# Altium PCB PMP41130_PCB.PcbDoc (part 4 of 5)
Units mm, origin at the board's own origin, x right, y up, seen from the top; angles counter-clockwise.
Board outline 74.13 x 200.91 mm, 6 copper layers (Top Layer, Layer 1, Inside Layer 1, Inside Layer 2, Layer 2, Bottom Layer), stack 2.208 mm thick; 356 components, 162 nets, 889 pads, 1511 vias.
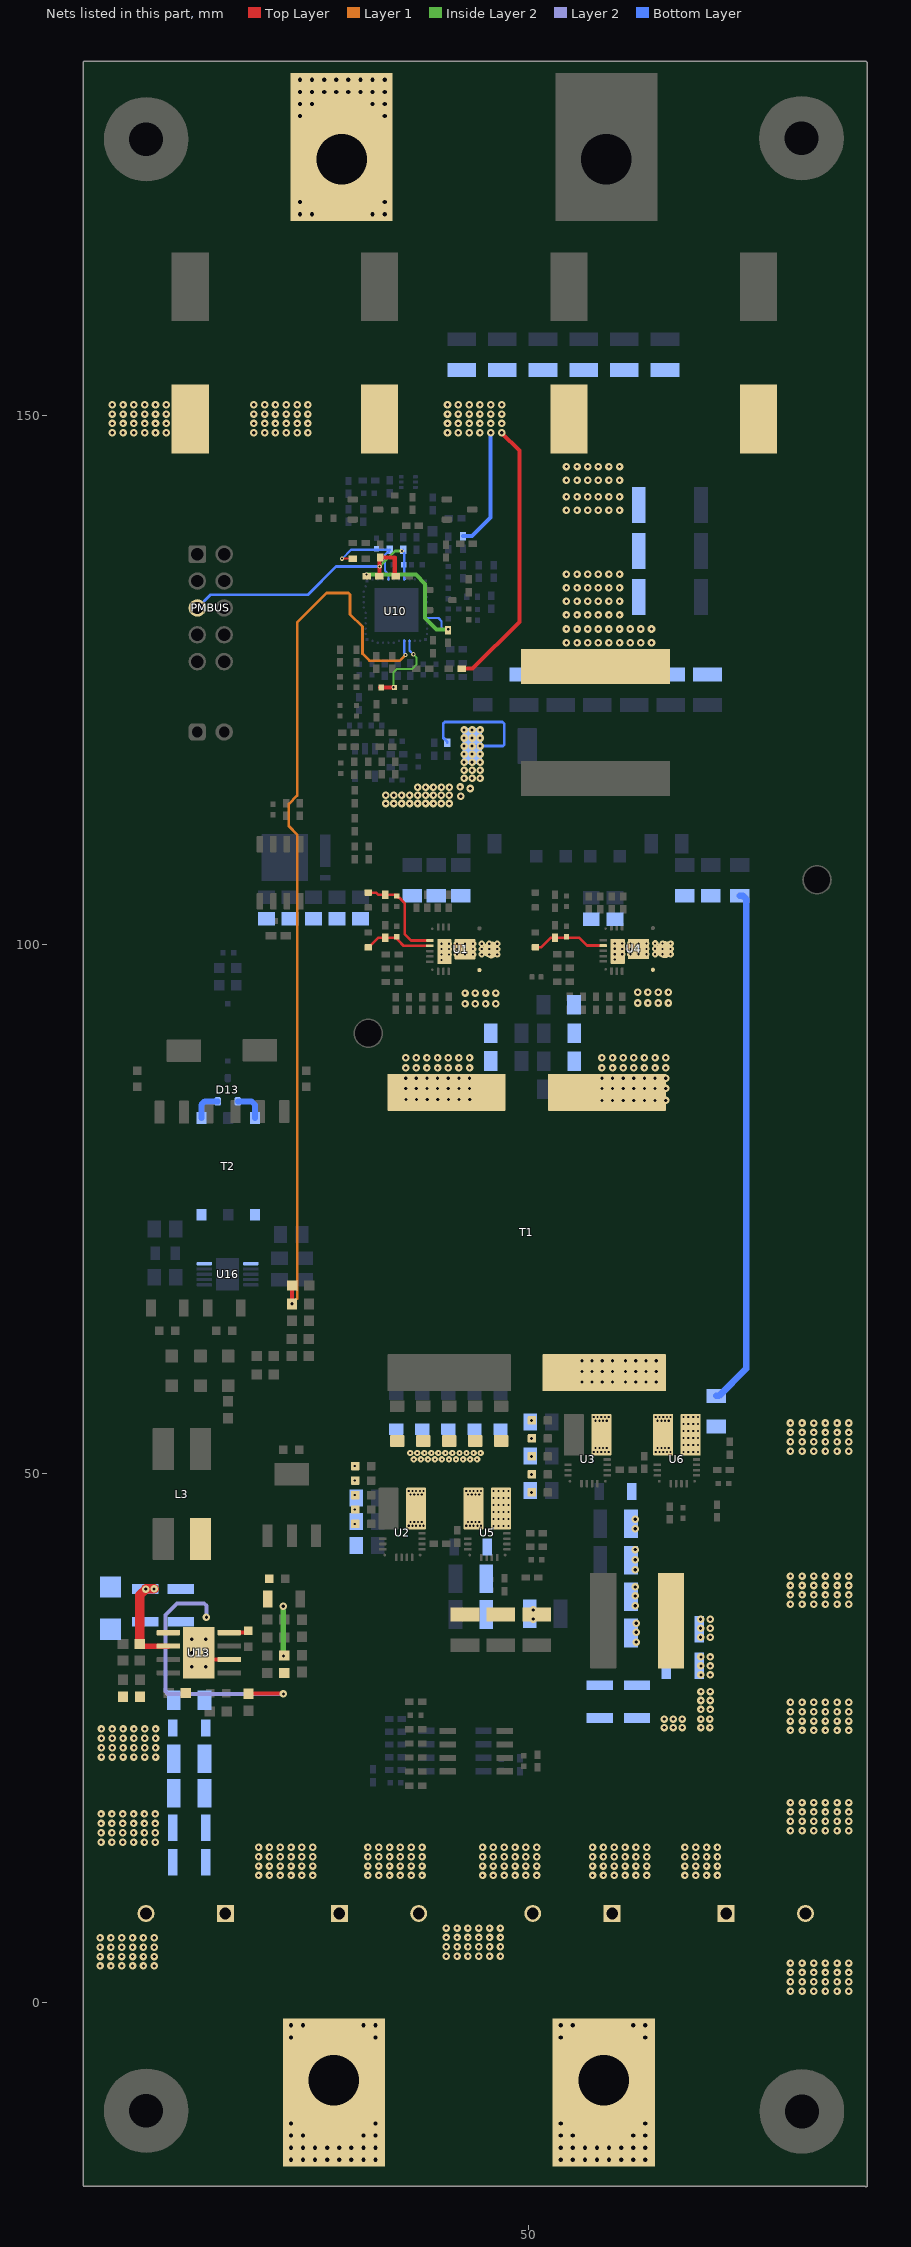
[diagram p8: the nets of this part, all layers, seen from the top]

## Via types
v1: diameter 0.711, hole 0.305, Top Layer to Bottom Layer, tented both sides, 1055 vias
v2: diameter 0.457, hole 0.203, Top Layer to Bottom Layer, tented both sides, 161 vias
v3: diameter 0.813, hole 0.406, Top Layer to Bottom Layer, 112 vias
v4: diameter 0.406, hole 0.203, Top Layer to Bottom Layer, tented both sides, 78 vias
v5: diameter 0.61, hole 0.203, Top Layer to Bottom Layer, tented both sides, 71 vias
v6: diameter 0.5, hole 0.2, Top Layer to Bottom Layer, 28 vias
v7: diameter 0.63, hole 0.33, Top Layer to Bottom Layer, 6 vias

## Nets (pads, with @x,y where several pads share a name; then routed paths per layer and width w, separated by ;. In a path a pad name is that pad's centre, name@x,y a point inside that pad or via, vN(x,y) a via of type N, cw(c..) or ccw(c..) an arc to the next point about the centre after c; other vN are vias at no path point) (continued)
SR_GATE2: C87.1 D4.2 R43.2 U4.13 | length 7.1
  Top Layer w0.254: D4.2@50.658,99.696 50.66,99.698 51.202,99.698 52.095,100.592 52.095,100.6 52.569,100.6 53.594,100.6 54.808,100.6 55.54,99.867 U4.13@57.074,99.867
SR_GATE3: C97.1 D5.2 R61.2 U1.12 | length 9.5
  Top Layer w0.254: D5.2@34.856,104.87 35.604,104.87 35.822,104.652 R61.2@36.472,104.652 36.475,104.656 37.557,104.656 C97.1@37.557,104.555 37.73,104.382 37.792,104.382 38.318,103.856 38.318,100.919 38.895,100.342 U1.12@40.683,100.342
SR_GATE4: C98.1 D6.2 R64.2 U1.13 | length 6.6
  Top Layer w0.254: D6.2@34.856,99.696 34.906,99.696 35.079,99.869 35.079,99.887 35.791,100.6 R64.2@36.472,100.6 C98.1@37.596,100.6 ; C98.1@37.557,100.6 37.557,100.5 37.73,100.327 38.214,99.842 U1.13@40.683,99.842
SR_Source: C3.2 C4.2 C125.1 C141.1 C142.1 C143.1 C144.1 C145.1 R1.2 R2.2 R3.2 R4.2 R5.2 R6.2 R51.2 RSENSE1.1 U1.6 U4.6 | length 62
  Bottom Layer w0.254: R51.2@42.327,119.026 42.327,119.126 41.945,119.508 41.945,120.853 42.095,121.003 47.525,121.003 47.724,120.804 47.724,118.869 47.575,118.721 v1(45.432,118.721) v1(44.675,118.721)
  Bottom Layer w0.635: C125.1@67.752,57.297 68,57.297 70.584,59.882 70.584,104.249 70.252,104.582 R3.2@69.977,104.582
  other v1: 36.507,113.293 37.26,113.293 38.013,113.293 38.765,113.293 39.518,113.293 40.27,113.293 41.023,113.293 41.767,113.293 42.519,113.293 43.595,113.984 36.507,114.069 37.26,114.069 38.013,114.069 38.765,114.069 39.518,114.069 40.27,114.069 41.023,114.069 41.763,114.069 42.515,114.069 44.5,114.71 39.518,114.833 40.27,114.833 41.023,114.833 41.778,114.833 42.531,114.833 43.535,114.864 43.91,115.669 44.668,115.669 45.432,115.669 43.91,116.431 44.668,116.431 45.432,116.431 43.917,117.197 44.675,117.197 45.432,117.197 43.917,117.959 44.675,117.959 45.432,117.959 43.917,118.721 43.917,119.483 44.675,119.483 45.432,119.483 43.917,120.245 44.675,120.245 45.432,120.245
  other v5: 41.77,98.515 58.161,98.54 42.479,99.019 43.241,99.019 44.003,99.019 44.765,99.019 46.289,99.019 47.051,99.019 41.77,99.023 45.58,99.023 58.869,99.044 59.631,99.044 60.393,99.044 61.155,99.044 62.679,99.044 63.441,99.044 58.161,99.048 61.971,99.048 42.479,99.527 43.241,99.527 44.003,99.527 44.765,99.527 46.289,99.527 47.051,99.527 41.77,99.531 45.58,99.531 58.869,99.552 59.631,99.552 60.393,99.552 61.155,99.552 62.679,99.552 63.441,99.552 58.161,99.556 61.971,99.556 42.479,100.035 43.241,100.035 44.003,100.035 44.765,100.035 46.289,100.035 47.051,100.035 41.77,100.039 45.58,100.039 58.869,100.06 59.631,100.06 60.393,100.06 61.155,100.06 62.679,100.06 63.441,100.06 58.161,100.064 61.971,100.064
SW1: C1.1 C7.1 C9.1 C20.1 C21.1 C22.1 C29.1 C32.1 C53.1 C54.1 U2.6 U5.7
  other v2: 38.682,45.023 39.034,45.023 39.386,45.023 39.738,45.023 40.089,45.023 44.114,45.023 44.466,45.023 44.818,45.023 45.17,45.023 45.522,45.023 38.858,45.372 39.21,45.372 39.562,45.372 39.914,45.372 44.29,45.372 44.642,45.372 44.994,45.372 45.346,45.372 38.858,47.968 39.21,47.968 39.562,47.968 39.914,47.968 44.29,47.968 44.642,47.968 44.994,47.968 45.346,47.968 38.682,48.317 39.034,48.317 39.386,48.317 39.738,48.317 40.089,48.317 44.114,48.317 44.466,48.317 44.818,48.317 45.17,48.317 45.522,48.317
  other v5: 39.165,51.289 39.829,51.289 40.494,51.289 41.158,51.289 41.823,51.289 42.488,51.289 43.152,51.289 43.817,51.289 44.482,51.289 45.146,51.289 38.829,51.899 39.493,51.899 40.158,51.899 40.823,51.899 41.487,51.899 42.152,51.899 42.817,51.899 43.481,51.899 44.146,51.899 44.811,51.899 45.475,51.899
SW2: T1.2 U3.6 U6.7
  other v1: 55.051,58.608 56.018,58.608 56.986,58.608 57.954,58.608 59.173,58.608 60.141,58.608 61.109,58.608 62.077,58.608 55.051,59.613 56.018,59.613 56.986,59.613 57.954,59.613 59.173,59.613 60.141,59.613 61.109,59.613 62.077,59.613 55.051,60.619 56.018,60.619 56.986,60.619 57.954,60.619 59.173,60.619 60.141,60.619 61.109,60.619 62.077,60.619
  other v2: 56.177,52.006 56.529,52.006 56.88,52.006 57.232,52.006 57.584,52.006 62.033,52.006 62.385,52.006 62.737,52.006 63.088,52.006 63.44,52.006 56.353,52.356 56.704,52.356 57.056,52.356 57.408,52.356 62.209,52.356 62.561,52.356 62.912,52.356 63.264,52.356 56.353,54.951 56.704,54.951 57.056,54.951 57.408,54.951 62.209,54.951 62.561,54.951 62.912,54.951 63.264,54.951 56.177,55.301 56.529,55.301 56.88,55.301 57.232,55.301 57.584,55.301 62.033,55.301 62.385,55.301 62.737,55.301 63.088,55.301 63.44,55.301
SW3: R21.2 R22.2 R23.2 R24.2 T1.3 U4.5
  other v1: 56.946,85.221 57.951,85.221 58.957,85.221 59.963,85.221 60.969,85.221 61.974,85.221 62.98,85.221 56.943,86.363 57.949,86.363 58.955,86.363 59.96,86.363 60.966,86.363 61.972,86.363 62.978,86.363 56.943,87.331 57.949,87.331 58.955,87.331 59.96,87.331 60.966,87.331 61.972,87.331 62.978,87.331 56.943,88.299 57.949,88.299 58.955,88.299 59.96,88.299 60.966,88.299 61.972,88.299 62.978,88.299 56.943,89.267 57.949,89.267 58.955,89.267 59.96,89.267 60.966,89.267 61.972,89.267 62.978,89.267 60.324,94.434 61.292,94.434 62.26,94.434 63.228,94.434 60.324,95.44 61.292,95.44 62.26,95.44 63.228,95.44
SW4: C30.2 C31.2 T1.4 U1.5
  other v1: 38.413,85.314 39.419,85.314 40.425,85.314 41.43,85.314 42.436,85.314 43.442,85.314 44.448,85.314 38.397,86.363 39.403,86.363 40.409,86.363 41.414,86.363 42.42,86.363 43.426,86.363 44.431,86.363 38.397,87.331 39.403,87.331 40.409,87.331 41.414,87.331 42.42,87.331 43.426,87.331 44.431,87.331 38.397,88.299 39.403,88.299 40.409,88.299 41.414,88.299 42.42,88.299 43.426,88.299 44.431,88.299 38.397,89.267 39.403,89.267 40.409,89.267 41.414,89.267 42.42,89.267 43.426,89.267 44.431,89.267 44.01,94.371 44.978,94.371 45.946,94.371 46.914,94.371 44.01,95.376 44.978,95.376 45.946,95.376 46.914,95.376
SW_AUX: C130.2 L3.4 R114.2 U13.8 | length 29.5
  Top Layer w0.381: U13.8@21.449,34.931 23.319,34.931 C130.2@23.514,35.126 ; R114.2@23.518,29.153 26.831,29.153 v1@26.84,29.161
  Layer 2 w0.381: v1(19.557,36.38) 19.557,37.461 19.334,37.684 16.759,37.684 15.678,36.603 15.678,29.344 15.901,29.121 v1(26.84,29.121)
TEMP: C118.1 FB6.2 U10.3 | length 7.7
  Top Layer w0.381: FB6.2@35.973,124.254 C118.1@37.247,124.254
  Inside Layer 2 w0.203: v4(37.239,124.278) 37.239,125.709 37.525,125.995 38.988,125.995 39.433,126.44 39.433,127.08 39.12,127.393 v4(39.12,127.4)
  Bottom Layer w0.203: U10.3@38.761,128.67 38.761,127.759 v4(39.12,127.4)
TMS: C120.1 R98.1 R104.2 U10.24 | length 9
  Top Layer w0.203: v4(32.385,136.434) R98.1@33.407,136.434
  Bottom Layer w0.203: v4(32.385,136.434) 33.225,137.274 35.646,137.274 36.696,137.274 R104.2@36.763,137.207 ; U10.24@36.761,134.474 36.761,134.983 36.44,135.304 36.44,136.819 36.596,136.976 36.696,136.976 36.795,137.075 36.795,137.175 R104.2@36.894,137.274
TransB1: T2.1 U16.1
TransB3: T2.3 U16.10
TransB4: D13.2 T2.4 | length 2.9
  Bottom Layer w0.559: T2.4@19.081,83.562 19.081,84.812 19.408,85.139 D13.2@20.633,85.139
TransB6: D13.1 T2.6 | length 3
  Bottom Layer w0.559: D13.1@22.533,85.139 23.824,85.139 24.151,84.812 24.151,83.571 T2.6@24.161,83.562
V33A: C104.1 C105.1 R70.2 U10.37 | length 14.6
  Inside Layer 2 w0.381: v4(34.695,134.931) 39.369,134.931 40.239,134.061 40.239,130.844 41.323,129.76 v4(42.419,129.76)
  Bottom Layer w0.203: U10.37@40.423,130.82 41.491,130.82 41.781,130.53 41.781,129.886 41.9,129.767 C105.1@42.412,129.767
V33D: C99.1 C102.1 C103.1 PMBUS.5 R67.1 R70.1 U10.27 | length 29.5
  Top Layer w0.381: R70.1@35.898,134.757 35.935,134.794 35.935,136.472 R67.1@36.007,136.544 37.362,136.544 37.362,134.866 C99.1@37.472,134.757
  Inside Layer 2 w0.254: v4(35.935,135.694) 37.398,137.157 38.007,137.157 v4@38.036,137.128
  Bottom Layer w0.203: v4(38.034,137.157) 38.095,137.095 38.141,137.095 38.261,136.976 U10.27@38.261,134.483 ; C102.1@38.157,137.157 C102.1@38.157,137.274
  Bottom Layer w0.254: PMBUS.5@18.699,131.778 19.943,133.023 29.145,133.023 31.817,135.694 v4(35.935,135.694)
VIN_NEG: C10.2 C11.2 C12.2 C13.2 C14.1 C15.1 C16.1 C17.1 C18.1 C19.1 C33.2 C34.2 C35.2 C36.2 C37.1 C38.1 C39.2 C40.2 C41.2 C42.2 C43.2 C45.2 C47.2 C48.2 C64.1 C65.1 C66.1 C67.1 C68.1 C69.1 C70.1 C71.1 C72.1 C73.1 C123.1 C124.1 C125.2 C133.2 C135.2 C136.2 C137.2 C138.2 C155.2 C156.2 C157.2 C158.2 C159.2 C160.1 D11.2 R117.1 R120.1 R121.1 R122.1 T5.1 U5.6 U6.6 U13.1 U13.6 U13.9 | length 7.9
  Top Layer w0.381: U13.9@18.575,33.026 19.21,32.391 U13.6@21.449,32.391
  Inside Layer 2 w0.508: v1(26.813,37.413) 26.826,37.399 26.826,32.725 v1(26.84,32.711)
  other v1: 74.768,1.025 75.87,1.025 76.972,1.025 78.074,1.025 79.177,1.025 80.279,1.025 74.768,1.913 75.87,1.913 76.972,1.913 78.074,1.913 79.177,1.913 80.279,1.913 74.768,2.8 75.87,2.8 76.972,2.8 78.074,2.8 79.177,2.8 80.279,2.8 9.508,3.411 10.532,3.411 11.556,3.411 12.579,3.411 13.603,3.411 14.626,3.411 74.768,3.688 75.87,3.688 76.972,3.688 78.074,3.688 79.177,3.688 80.279,3.688 9.508,4.299 10.532,4.299 11.556,4.299 12.579,4.299 13.603,4.299 14.626,4.299 42.231,4.333 43.255,4.333 44.279,4.333 45.302,4.333 46.326,4.333 47.349,4.333 9.508,5.186 10.532,5.186 11.556,5.186 12.579,5.186 13.603,5.186 14.626,5.186 42.231,5.221 43.255,5.221 44.279,5.221 45.302,5.221 46.326,5.221 47.349,5.221 9.508,6.074 10.532,6.074 11.556,6.074 12.579,6.074 13.603,6.074 14.626,6.074 42.231,6.108 43.255,6.108 44.279,6.108 45.302,6.108 46.326,6.108 47.349,6.108 42.231,6.996 43.255,6.996 44.279,6.996 45.302,6.996 46.326,6.996 47.349,6.996 9.604,15.114 10.627,15.114 11.651,15.114 12.675,15.114 13.698,15.114 14.722,15.114 9.604,16.001 10.627,16.001 11.651,16.001 12.675,16.001 13.698,16.001 14.722,16.001 74.768,16.194 75.87,16.194 76.972,16.194 78.074,16.194 79.177,16.194 80.279,16.194 9.604,16.889 10.627,16.889 11.651,16.889 12.675,16.889 13.698,16.889 14.722,16.889 74.768,17.081 75.87,17.081 76.972,17.081 78.074,17.081 79.177,17.081 80.279,17.081 9.604,17.777 10.627,17.777 11.651,17.777 12.675,17.777 13.698,17.777 14.722,17.777 74.768,17.969 75.87,17.969 76.972,17.969 78.074,17.969 79.177,17.969 80.279,17.969 74.768,18.857 75.87,18.857 76.972,18.857 78.074,18.857 79.177,18.857 80.279,18.857 9.636,23.159 10.659,23.159 11.683,23.159 12.706,23.159 13.73,23.159 14.754,23.159 9.636,24.047 10.659,24.047 11.683,24.047 12.706,24.047 13.73,24.047 14.754,24.047 9.636,24.935 10.659,24.935 11.683,24.935 12.706,24.935 13.73,24.935 14.754,24.935 74.768,25.67 75.87,25.67 76.972,25.67 78.074,25.67 79.177,25.67 80.279,25.67 9.636,25.822 10.659,25.822 11.683,25.822 12.706,25.822 13.73,25.822 14.754,25.822 74.768,26.558 75.87,26.558 76.972,26.558 78.074,26.558 79.177,26.558 80.279,26.558 74.768,27.446 75.87,27.446 76.972,27.446 78.074,27.446 79.177,27.446 80.279,27.446 74.768,28.334 75.87,28.334 76.972,28.334 78.074,28.334 79.177,28.334 80.279,28.334 60.199,34.027 60.199,34.949 60.199,35.808 50.457,36.202 50.457,37.06 60.104,37.461 74.768,37.597 75.87,37.597 76.972,37.597 78.074,37.597 79.177,37.597 80.279,37.597 60.104,38.384 74.768,38.485 75.87,38.485 76.972,38.485 78.074,38.485 79.177,38.485 80.279,38.485 60.104,39.242 74.768,39.373 75.87,39.373 76.972,39.373 78.074,39.373 79.177,39.373 80.279,39.373 74.768,40.26 75.87,40.26 76.972,40.26 78.074,40.26 79.177,40.26 80.279,40.26 60.104,40.864 60.104,41.818 60.104,42.772 60.104,44.744 60.104,45.634 50.284,48.169 50.284,49.87 50.284,51.571 74.768,52.07 75.87,52.07 76.972,52.067 78.074,52.07 79.177,52.07 79.177,52.07 80.279,52.07 74.768,52.958 75.87,52.958 76.972,52.954 78.074,52.958 79.177,52.958 79.177,52.958 80.279,52.958 50.284,53.272 74.768,53.846 75.87,53.846 76.972,53.842 78.074,53.846 79.177,53.846 79.177,53.846 80.279,53.846 74.768,54.733 75.87,54.733 76.972,54.73 78.074,54.733 79.177,54.733 79.177,54.733 80.279,54.733 50.284,54.973
  other v2: 46.706,45 47.171,45 47.637,45 48.102,45 33.576,45.189 46.706,45.66 47.171,45.66 47.637,45.66 48.102,45.66 46.706,46.319 47.171,46.319 47.637,46.319 48.102,46.319 33.576,46.556 46.706,46.978 47.171,46.978 47.637,46.978 48.102,46.978 46.706,47.637 47.171,47.637 47.637,47.637 48.102,47.637 33.576,47.924 46.706,48.296 47.171,48.296 47.637,48.296 48.102,48.296 33.576,49.291 33.576,50.659 64.644,52.007 65.11,52.007 65.575,52.007 66.04,52.007 64.644,52.666 65.11,52.666 65.575,52.666 66.04,52.666 64.644,53.325 65.11,53.325 65.575,53.325 66.04,53.325 64.644,53.984 65.11,53.984 65.575,53.984 66.04,53.984 64.644,54.644 65.11,54.644 65.575,54.644 66.04,54.644 64.644,55.303 65.11,55.303 65.575,55.303 66.04,55.303
  other v3: 53.05,-14.903 54.193,-14.903 55.336,-14.903 56.479,-14.903 57.622,-14.903 58.765,-14.903 59.908,-14.903 61.051,-14.903 53.05,-13.76 54.193,-13.76 55.336,-13.76 56.479,-13.76 57.622,-13.76 58.765,-13.76 59.908,-13.76 61.051,-13.76 53.05,-12.617 54.193,-12.617 59.908,-12.617 61.051,-12.617 53.05,-11.474 61.051,-11.474 53.05,-3.346 61.051,-3.346 53.05,-2.203 54.193,-2.203 59.908,-2.203 61.051,-2.203
  other v7: 18.189,31.71 19.489,31.71 18.189,33.01 19.489,33.01 18.189,34.31 19.489,34.31
VIN_POS: C10.1 C11.1 C12.1 C13.1 C33.1 C34.1 C35.1 C36.1 C137.1 C138.1 C155.1 C156.1 C157.1 C158.1 C159.1 C160.2 D11.1 L1.1 R113.2 T3.1 U13.2 | length 9
  Top Layer w0.508: R113.2@13.273,33.887 13.514,33.645 U13.2@15.964,33.645
  Top Layer w0.889: R113.2@13.257,33.887 13.257,38.464 13.818,39.025 v1(13.818,39.041) 13.824,39.047 14.608,39.047 v1(14.614,39.054)
  other v1: 24.487,11.965 25.51,11.965 26.534,11.965 27.557,11.965 28.581,11.965 29.604,11.965 34.822,11.965 35.845,11.965 36.869,11.965 37.893,11.965 38.916,11.965 39.94,11.965 45.66,11.965 46.683,11.965 47.707,11.965 48.73,11.965 49.754,11.965 50.777,11.965 56.065,11.965 57.088,11.965 58.112,11.965 59.136,11.965 60.159,11.965 61.183,11.965 64.79,11.965 65.814,11.965 66.837,11.965 67.861,11.965 24.487,12.853 25.51,12.853 26.534,12.853 27.557,12.853 28.581,12.853 29.604,12.853 34.822,12.853 35.845,12.853 36.869,12.853 37.893,12.853 38.916,12.853 39.94,12.853 45.66,12.853 46.683,12.853 47.707,12.853 48.73,12.853 49.754,12.853 50.777,12.853 56.065,12.853 57.088,12.853 58.112,12.853 59.136,12.853 60.159,12.853 61.183,12.853 64.79,12.853 65.814,12.853 66.837,12.853 67.861,12.853 24.487,13.741 25.51,13.741 26.534,13.741 27.557,13.741 28.581,13.741 29.604,13.741 34.822,13.741 35.845,13.741 36.869,13.741 37.893,13.741 38.916,13.741 39.94,13.741 45.66,13.741 46.683,13.741 47.707,13.741 48.73,13.741 49.754,13.741 50.777,13.741 56.065,13.741 57.088,13.741 58.112,13.741 59.136,13.741 60.159,13.741 61.183,13.741 64.79,13.741 65.814,13.741 66.837,13.741 67.861,13.741 24.487,14.628 25.51,14.628 26.534,14.628 27.557,14.628 28.581,14.628 29.604,14.628 34.822,14.628 35.845,14.628 36.869,14.628 37.893,14.628 38.916,14.628 39.94,14.628 45.66,14.628 46.683,14.628 47.707,14.628 48.73,14.628 49.754,14.628 50.777,14.628 56.065,14.628 57.088,14.628 58.112,14.628 59.136,14.628 60.159,14.628 61.183,14.628 64.79,14.628 65.814,14.628 66.837,14.628 67.861,14.628 62.838,25.949 63.688,25.949 64.537,25.949 66.3,25.949 67.149,25.949 62.843,26.748 63.693,26.748 64.542,26.748 66.305,26.748 67.154,26.748 66.305,27.654 67.195,27.654 66.305,28.503 67.195,28.503 66.305,29.352 67.195,29.352 66.305,30.92 67.195,30.92 66.305,31.769 67.195,31.769 66.305,32.618 67.195,32.618 66.273,34.482 67.195,34.482 66.273,35.331 67.195,35.331 66.273,36.18 67.195,36.18
  other v3: 27.546,-14.903 28.689,-14.903 29.832,-14.903 30.975,-14.903 32.118,-14.903 33.261,-14.903 34.404,-14.903 35.547,-14.903 27.546,-13.76 28.689,-13.76 29.832,-13.76 30.975,-13.76 32.118,-13.76 33.261,-13.76 34.404,-13.76 35.547,-13.76 27.546,-12.617 28.689,-12.617 34.404,-12.617 35.547,-12.617 27.546,-11.474 35.547,-11.474 27.546,-3.346 35.547,-3.346 27.546,-2.203 28.689,-2.203 34.404,-2.203 35.547,-2.203
VIN_Scale: C140.1 R126.2 U10.4 | length 85.3
  Top Layer w0.381: R126.2@27.632,65.981 v1(27.657,66.007) 27.657,67.701 C140.1@27.683,67.726
  Layer 1 w0.254: v1(27.657,66.007) 28.144,66.493 28.144,110.349 27.349,111.144 27.349,113.243 28.144,114.038 28.144,130.415 30.91,133.182 32.988,133.182 33.136,133.033 33.136,131.178 34.313,130.002 34.313,127.458 34.981,126.79 37.838,126.79 v4(38.381,127.333)
  Bottom Layer w0.203: U10.4@38.261,128.67 38.261,127.508 38.381,127.388 v4(38.381,127.333)
VOUT: C23.2 C24.2 C25.2 C26.2 C27.2 C28.2 C49.1 C50.1 C51.1 C52.1 C57.2 C58.2 C59.2 C60.2 C61.2 C62.2 L2.2 R7.2 R8.1 R10.2 R71.2 R74.2 T4.1 | length 37.5
  Top Layer w0.381: R74.2@43.675,126.028 43.692,126.045 44.73,126.045 49.132,130.447 49.132,146.661 v1(47.466,148.327)
  Top Layer w0.508: L2.2@56.14,126.028 L2.2@56.351,126.238
  Bottom Layer w0.381: R71.2@43.807,138.557 44.65,138.557 46.435,140.342 v1@46.435,148.319
  other v1: 53.586,128.496 54.591,128.496 55.597,128.496 56.603,128.496 57.609,128.496 58.614,128.496 59.62,128.496 60.626,128.496 61.631,128.496 53.586,129.786 54.591,129.786 55.597,129.786 56.603,129.786 57.609,129.786 58.614,129.786 59.62,129.786 60.626,129.786 61.631,129.786 53.586,131.121 54.591,131.121 55.597,131.121 56.603,131.121 57.609,131.121 58.614,131.121 53.586,132.411 54.591,132.411 55.597,132.411 56.603,132.411 57.609,132.411 58.614,132.411 53.586,133.68 54.591,133.68 55.597,133.68 56.603,133.68 57.609,133.68 58.614,133.68 53.586,134.971 54.591,134.971 55.597,134.971 56.603,134.971 57.609,134.971 58.614,134.971 53.586,141.007 54.591,141.007 55.597,141.007 56.603,141.007 57.609,141.007 58.614,141.007 53.586,142.298 54.591,142.298 55.597,142.298 56.603,142.298 57.609,142.298 58.614,142.298 53.586,143.849 54.591,143.849 55.597,143.849 56.603,143.849 57.609,143.849 58.614,143.849 53.586,145.139 54.591,145.139 55.597,145.139 56.603,145.139 57.609,145.139 58.614,145.139 10.653,148.327 11.677,148.327 12.7,148.327 13.724,148.327 14.748,148.327 15.771,148.327 24.041,148.327 25.065,148.327 26.089,148.327 27.112,148.327 28.136,148.327 29.159,148.327 42.349,148.327 43.372,148.327 44.396,148.327 45.419,148.327 46.443,148.327 10.653,149.215 11.677,149.215 12.7,149.215 13.724,149.215 14.748,149.215 15.771,149.215 24.041,149.215 25.065,149.215 26.089,149.215 27.112,149.215 28.136,149.215 29.159,149.215 42.349,149.215 43.372,149.215 44.396,149.215 45.419,149.215 46.443,149.215 47.466,149.215 10.653,150.102 11.677,150.102 12.7,150.102 13.724,150.102 14.748,150.102 15.771,150.102 24.041,150.102 25.065,150.102 26.089,150.102 27.112,150.102 28.136,150.102 29.159,150.102 42.349,150.102 43.372,150.102 44.396,150.102 45.419,150.102 46.443,150.102 47.466,150.102 10.653,150.99 11.677,150.99 12.7,150.99 13.724,150.99 14.748,150.99 15.771,150.99 24.041,150.99 25.065,150.99 26.089,150.99 27.112,150.99 28.136,150.99 29.159,150.99 42.349,150.99 43.372,150.99 44.396,150.99 45.419,150.99 46.443,150.99 47.466,150.99
  other v3: 28.404,168.998 29.547,168.998 35.262,168.998 36.405,168.998 28.404,170.141 36.405,170.141 28.404,178.269 36.405,178.269 28.404,179.412 29.547,179.412 35.262,179.412 36.405,179.412 28.404,180.555 29.547,180.555 30.69,180.555 31.833,180.555 32.976,180.555 34.119,180.555 35.262,180.555 36.405,180.555 28.404,181.698 29.547,181.698 30.69,181.698 31.833,181.698 32.976,181.698 34.119,181.698 35.262,181.698 36.405,181.698
pads on no net: H1.1 H2.1 H3.1 H4.1 H5.0 H6.0 H7.0 H8.0 PMBUS.1 PMBUS.2 PMBUS.3 PMBUS.4 Q2.1 Q2.2 Q2.6 U2.1 U2.5 U2.9 U2.10 U2.11 U2.12 U2.13 U2.15 U3.1 U3.5 U3.9 U3.10 U3.11 U3.12 U3.13 U3.15 U5.1 U5.5 U5.11 U5.12 U5.13 U5.15 U6.1 U6.5 U6.11 U6.12 U6.13 U6.15 U10.21 U10.22 U10.23 U10.25 U10.39 U16.5 U16.6

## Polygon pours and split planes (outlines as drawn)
NetC30_1 on Bottom Layer "BOTTOM_LAYER_NETC30_1_P012" (solid, remove dead copper, pour order 12): 52.398,95.202 52.398,85.136 48.601,85.136 48.601,95.202
SR_Source on Bottom Layer "BOTTOM_LAYER_SR_SOURCE_P010" (solid, remove dead copper, pour order 10): 20 vertices, not listed, extent 23.66,97.726 70.936,105.233
SR_Drain on Bottom Layer "BOTTOM_LAYER_SR_DRAIN_P024" (solid, remove dead copper, pour order 24): 49.646,114.037 46.114,110.506 46.114,109.745 62.489,109.745 62.489,111.46 62.489,114.037
SR_Source on Bottom Layer "BOTTOM_LAYER_SR_SOURCE_P196" (solid, remove dead copper, pour order 196): 43.44,112.925 44.521,112.925 45.92,114.324 45.92,120.617 43.44,120.617
NetC89_2 on Bottom Layer "BOTTOM_LAYER_NETC89_2_P026" (solid, remove dead copper, pour order 26): 37.773,116.197 37.773,116.907 38.641,116.907 38.641,117.091 38.65,117.1 40.471,117.1 40.471,116.907 42.033,116.907 42.033,118.23 42.622,118.23 42.622,116.197
GND on Bottom Layer "BOTTOM_LAYER_GND_P126" (solid, remove dead copper, pour order 126): 9.68,112.944 8.586,114.038 8.586,140.941 10.971,143.326 46.6,143.326 46.6,123.769 44.489,123.769 44.489,121.924 40.532,121.924 40.532,118.871 35.501,118.871 35.501,112.944
SR_Drain on Bottom Layer "BOTTOM_LAYER_SR_DRAIN_P018" (solid, remove dead copper, pour order 18): 62.485,110.508 46.114,110.508 46.114,102.499 47.818,102.499 47.818,107.687 51.558,107.687 51.558,109.46 57.816,109.46 57.816,107.687 58.116,107.388 60.802,107.388 60.802,102.499 62.485,102.499
GND on Bottom Layer "BOTTOM_LAYER_GND_P092" (solid, remove dead copper, pour order 92): 8.529,73.333 31.61,73.333 31.61,27.444 32.708,26.346 41.93,26.346 42.337,25.939 42.337,18.709 42.009,18.381 30.37,18.381 29.861,18.89 29.861,43.503 28.823,44.542 8.529,44.542
VIN_NEG on Bottom Layer "BOTTOM_LAYER_VIN_NEG_P107" (solid, remove dead copper, pour order 107): 23 vertices, not listed, extent 38.686,-15.551 81.124,55.524
SW1 on Bottom Layer "BOTTOM_LAYER_SW1_P007" (solid, remove dead copper, pour order 7): 48.333,54.82 48.333,49.589 45.945,49.589 45.761,49.405 45.761,44.776 45.672,44.686 38.445,44.686 38.445,49.31 38.295,49.46 36.062,49.46 36.062,54.82
VIN_NEG on Bottom Layer "BOTTOM_LAYER_VIN_NEG_P009" (solid, remove dead copper, pour order 9): 34.404,51.301 33.105,51.301 33.105,28.944 34.404,28.944
SR_Drain on Bottom Layer "BOTTOM_LAYER_SR_DRAIN_P071" (solid, remove dead copper, pour order 71): 18 vertices, not listed, extent 15.074,81.569 22.179,99.476
VIN_NEG on Bottom Layer "BOTTOM_LAYER_VIN_NEG_P006" (solid, remove dead copper, pour order 6): 50.784,55.683 50.784,35.488 50.498,35.202 45.284,35.202 45.284,44.108 46.461,44.108 46.461,48.686 46.655,48.88 48.978,48.88 48.978,55.683
AGND on Bottom Layer "BOTTOM_LAYER_AGND_P131" (solid, remove dead copper, pour order 131): 64.383,123.387 70.181,123.387 70.789,123.995 70.789,163.234 72.856,165.301 79.963,165.301 81.251,164.013 81.251,117.557 80.735,116.963 64.383,116.963 64.383,123.306
VOUT on Bottom Layer "BOTTOM_LAYER_VOUT_P116" (solid, remove dead copper, pour order 116): 27.508,182.314 27.508,168.35 24.836,165.587 9.437,165.587 8.586,164.586 8.586,149.337 8.586,147.683 37.143,147.683 37.143,168.449 37.143,182.314
VOUT on Bottom Layer "BOTTOM_LAYER_VOUT_P031" (solid, remove dead copper, pour order 31): 19 vertices, not listed, extent 8.046,124.818 68.612,154.902
SR_Source on Bottom Layer "BOTTOM_LAYER_SR_SOURCE_P021" (solid, remove dead copper, pour order 21): 36.138,115.214 36.138,112.921 44.077,112.921 44.077,115.214
VIN_POS on Bottom Layer "BOTTOM_LAYER_VIN_POS_P000" (solid, remove dead copper, pour order 0): 69.612,36.87 65.3,36.87 65.3,28.666 64.389,27.755 55.383,27.755 54.936,27.308 54.936,18.364 68.655,18.364 69.612,19.32
VIN_NEG on Bottom Layer "BOTTOM_LAYER_VIN_NEG_P001" (solid, remove dead copper, pour order 1): 63.799,39.686 63.799,29.55 63.194,28.944 33.105,28.944 33.105,30.92 59.042,30.92 59.042,39.686
VIN_NEG on Bottom Layer "BOTTOM_LAYER_VIN_NEG_P002" (solid, remove dead copper, pour order 2): 81.092,55.524 81.092,38.733 59.042,38.733 59.042,50.806 59.086,50.849 64.397,50.849 64.397,55.524
SW2 on Bottom Layer "BOTTOM_LAYER_SW2_P003" (solid, remove dead copper, pour order 3): 65.3,56.287 65.3,62.364 51.494,62.363 51.494,56.86 55.938,56.86 55.938,51.644 63.697,51.644 63.697,56.001 63.983,56.287
HS_Drain on Bottom Layer "BOTTOM_LAYER_HS_DRAIN_P004" (solid, remove dead copper, pour order 4): 55.238,55.715 55.238,51.04 55.429,50.849 57.496,50.849 57.496,32.237 57.259,31.999 51.586,31.999 51.586,55.529 51.772,55.715
NetC1_2 on Bottom Layer "BOTTOM_LAYER_NETC1_2_P005" (solid, remove dead copper, pour order 5): 50.784,56.86 50.784,62.364 36.062,62.364 36.062,56.86
HS_Drain on Bottom Layer "BOTTOM_LAYER_HS_DRAIN_P008" (solid, remove dead copper, pour order 8): 35.213,48.623 35.213,32.323 35.537,31.999 52.372,31.999 52.372,34.622 44.169,34.622 43.79,35.001 43.79,44.008 43.69,44.108 37.733,44.108 37.733,48.623
SW3 on Bottom Layer "BOTTOM_LAYER_SW3_P011" (solid, remove dead copper, pour order 11): 53.594,95.91 53.594,84.253 63.641,84.253 63.641,95.91
NetC5_1 on Bottom Layer "BOTTOM_LAYER_NETC5_1_P015" (solid, remove dead copper, pour order 15): 63.623,110.405 63.623,106.784 70.951,106.784 70.951,110.405
NetC6_1 on Bottom Layer "BOTTOM_LAYER_NETC6_1_P016" (solid, remove dead copper, pour order 16): 38.074,106.85 44.575,106.85 44.575,110.444 38.074,110.444
SW4 on Bottom Layer "BOTTOM_LAYER_SW4_P017" (solid, remove dead copper, pour order 17): 47.568,95.822 47.568,84.253 37.96,84.253 37.96,95.822
NetC3_1 on Bottom Layer "BOTTOM_LAYER_NETC3_1_P019" (solid, remove dead copper, pour order 19): 59.004,103.734 59.004,105.229 56.518,105.229 56.518,108.833 56.342,109.009 53.017,109.009 52.824,108.815 52.824,107.388 54.926,107.388 55.037,107.258 55.037,103.734
AGND on Bottom Layer "BOTTOM_LAYER_AGND_P020" (solid, remove dead copper, pour order 20): 68.623,123.324 44.744,123.323 44.744,121.924 48.97,121.924 48.97,116.963 66.93,116.963 68.612,118.646
NetC89_1 on Bottom Layer "BOTTOM_LAYER_NETC89_1_P025" (solid, remove dead copper, pour order 25): 37.773,118.299 37.773,117.589 38.641,117.589 38.641,117.405 38.65,117.396 40.471,117.396 41.429,117.396 41.429,118.299
NetC91_1 on Bottom Layer "BOTTOM_LAYER_NETC91_1_P027" (solid, remove dead copper, pour order 27): 37.381,117.589 37.381,119.525 35.279,119.525 35.193,119.438 35.193,117.725 35.329,117.589 35.501,117.589
NetC81_2 on Bottom Layer "BOTTOM_LAYER_NETC81_2_P030" (solid, remove dead copper, pour order 30): 37.386,117.091 37.386,115.155 35.198,115.155 35.198,116.948 35.341,117.091
NetC3_1 on Bottom Layer "BOTTOM_LAYER_NETC3_1_P032" (solid, remove dead copper, pour order 32): 68.567,130.828 65.496,130.828 65.219,131.105 65.219,143.068 65.418,143.267 68.146,143.267 68.548,143.267
SR_Source on Bottom Layer "BOTTOM_LAYER_SR_SOURCE_P035" (solid, remove dead copper, pour order 35): 70.935,96.95 70.358,96.95 69.584,97.724 69.584,102.176 70.935,102.176
VIN_NEG on Bottom Layer "BOTTOM_LAYER_VIN_NEG_P060" (solid, remove dead copper, pour order 60): 8.529,-0.286 16.566,-0.286 16.566,36.698 8.529,36.698
VIN_POS on Bottom Layer "BOTTOM_LAYER_VIN_POS_P061" (solid, remove dead copper, pour order 61): 19.373,7.6 24.741,7.6 24.741,29.448 19.373,29.448
VIN_NEG on Bottom Layer "BOTTOM_LAYER_VIN_NEG_P063" (solid, remove dead copper, pour order 63): 15.678,31.104 20.321,31.104 20.321,36.412 20.035,36.698 15.678,36.698
VIN_POS on Bottom Layer "BOTTOM_LAYER_VIN_POS_P064" (solid, remove dead copper, pour order 64): 21.434,38.256 21.911,37.779 21.911,29.473 20.581,28.144 18.858,28.144 18.858,27.821 18.98,27.698 23.495,27.698 24.748,28.952 24.748,39.171 23.729,40.19 8.898,40.19 8.529,39.821 8.529,38.256
TransB3 on Bottom Layer "BOTTOM_LAYER_TRANSB3_P068" (solid, remove dead copper, pour order 68): 18.607,69.632 18.445,69.795 18.445,75.018 20.157,75.018 20.157,69.715 20.073,69.632
NetC141_2 on Bottom Layer "BOTTOM_LAYER_NETC141_2_P072" (solid, remove dead copper, pour order 72): 29.225,110.444 29.32,110.349 29.32,106.119 29.893,105.547 34.943,105.547 35.261,105.229 35.261,103.903 35.092,103.734 23.66,103.734 23.66,110.276 23.828,110.444
TransB1 on Bottom Layer "BOTTOM_LAYER_TRANSB1_P073" (solid, remove dead copper, pour order 73): 24.518,69.632 24.681,69.795 24.681,75.018 22.969,75.018 22.969,69.715 23.052,69.632
VIN_POS on Bottom Layer "BOTTOM_LAYER_VIN_POS_P099" (solid, remove dead copper, pour order 99): 23 vertices, not listed, extent 19.373,-15.837 69.612,20.347
AGND on Bottom Layer "BOTTOM_LAYER_AGND_P117" (solid, remove dead copper, pour order 117): 41.605,165.301 41.605,156.524 57.563,156.524 69.612,156.524 70.852,155.538 81.124,155.538 81.124,163.679 79.502,165.301
AGND on Bottom Layer "BOTTOM_LAYER_AGND_P118" (solid, remove dead copper, pour order 118): 52.535,182.314 52.535,168.353 52.503,168.353 49.323,165.173 49.323,158.622 65.319,158.622 65.319,165.301 62.171,168.449 62.171,182.314
SR_Drain on Bottom Layer "BOTTOM_LAYER_SR_DRAIN_P128" (solid, remove dead copper, pour order 128): 30.274,110.412 30.274,107.328 30.338,107.264 35.85,107.264 36.052,107.467 36.052,110.412
HS_Drain on Top Layer "TOP_LAYER_HS_DRAIN_P047" (solid, remove dead copper, pour order 47): 51.494,55.654 51.363,55.523 51.363,47.658 53.035,47.658 53.035,50.659 54.272,50.659 55.27,51.592 55.27,55.654
SR_Drain on Top Layer "TOP_LAYER_SR_DRAIN_P216" (solid, remove dead copper, pour order 216): 34.439,110.407 34.439,108.832 36.243,108.832 36.243,110.407
VIN_NEG on Top Layer "TOP_LAYER_VIN_NEG_P215" (solid, remove dead copper, pour order 215): 24.264,35.458 9.856,35.458 8.077,33.68 8.077,23.66 27.221,23.66 30.847,27.285 30.847,41.221 30.268,41.822 24.264,41.822
VIN_POS on Top Layer "TOP_LAYER_VIN_POS_P100" (solid, remove dead copper, pour order 100): 69.696,40.693 62.24,40.693 62.24,16.193 61.201,15.153 61.201,6.297 69.696,6.297
VIN_POS on Top Layer "TOP_LAYER_VIN_POS_P101" (solid, remove dead copper, pour order 101): 21 vertices, not listed, extent 20.48,-15.837 68.67,15.201
VIN_NEG on Top Layer "TOP_LAYER_VIN_NEG_P045" (solid, remove dead copper, pour order 45): 49.624,55.654 49.624,51.007 49.275,50.659 46.601,50.659 46.448,50.506 46.448,44.68 49.212,44.68 50.767,46.235 50.767,55.654
VIN_NEG on Top Layer "TOP_LAYER_VIN_NEG_P048" (solid, remove dead copper, pour order 48): 64.397,55.589 64.462,55.654 81.128,55.654 81.128,51.659 64.397,51.659
HS_Drain on Top Layer "TOP_LAYER_HS_DRAIN_P108" (solid, remove dead copper, pour order 108): 21 vertices, not listed, extent 32.914,31.557 58.354,51.136
SR_Drain on Top Layer "TOP_LAYER_SR_DRAIN_P112" (solid, remove dead copper, pour order 112): 22 vertices, not listed, extent 43.491,101.267 64.524,117.345
GND on Top Layer "TOP_LAYER_GND_P109" (solid, remove dead copper, pour order 109): 17.432,83.064 9.318,83.064 8.173,84.209 8.173,142.425 47.192,142.425 47.192,131.36 44.203,128.487 44.203,125.709 39.592,125.709 39.02,125.136 39.02,115.657 31.13,115.623 31.13,85.83 28.427,83.127
SW_AUX on Top Layer "TOP_LAYER_SW_AUX_P074" (solid, remove dead copper, pour order 74): 17.993,45.789 19.957,45.789 19.957,41.822 23.978,41.822 23.978,34.616 17.993,34.616 17.993,40.68
VOUT on Top Layer "TOP_LAYER_VOUT_P143" (solid, remove dead copper, pour order 143): 48.178,124.627 48.178,127.267 49.164,128.253 50.627,129.715 50.627,151.594 51.931,152.898 51.937,152.892 56.23,152.892 63.281,152.892 63.281,128.414 64.587,127.108 64.587,124.627
PRI_AGND on Top Layer "TOP_LAYER_PRI_AGND_P091" (solid, remove dead copper, pour order 91): 47.984,44.316 49.266,44.316 51.141,46.191 53.035,46.191 53.035,37.439 46.399,37.439 44.704,39.134 44.704,41.334 45.773,42.403 47.626,42.403 47.626,43.957
SW2 on Top Layer "TOP_LAYER_SW2_P043" (solid, remove dead copper, pour order 43): 51.436,57.672 51.363,57.745 51.363,61.245 65.128,61.245 65.128,57.865 64.948,57.672 63.873,57.672 63.683,57.481 63.683,51.644 55.938,51.644 55.938,57.464 55.729,57.672
AGND on Top Layer "TOP_LAYER_AGND_P142" (solid, remove dead copper, pour order 142): 70.789,124.058 70.789,141.704 71.089,142.118 80.838,142.118 81.251,141.704 81.251,118.083 80.877,117.653 71.112,117.653 70.789,117.938
VIN_NEG on Top Layer "TOP_LAYER_VIN_NEG_P104" (solid, remove dead copper, pour order 104): 22 vertices, not listed, extent 38.733,-15.551 81.124,55.649
VIN_NEG on Top Layer "TOP_LAYER_VIN_NEG_P038" (solid, remove dead copper, pour order 38): 32.989,54.061 32.914,53.916 32.914,44.685 34.059,44.685 34.059,51.899 35.7,51.899 35.7,54.061
VIN_NEG on Top Layer "TOP_LAYER_VIN_NEG_P039" (solid, remove dead copper, pour order 39): 42.66,38.915 42.66,35.969 42.793,35.835 53.035,35.835 53.035,37.439 46.128,37.439 44.652,38.915
SW1 on Top Layer "TOP_LAYER_SW1_P042" (solid, remove dead copper, pour order 42): 36.996,51.899 36.889,52.006 36.889,53.973 36.977,54.061 48.242,54.061 48.348,53.955 48.348,52.025 48.223,51.899 46.019,51.899 45.784,51.664 45.784,44.68 38.447,44.68 38.447,51.74 38.288,51.899
NetC1_2 on Top Layer "TOP_LAYER_NETC1_2_P044" (solid, remove dead copper, pour order 44): 32.908,55.654 32.908,61.228 48.348,61.228 48.348,55.734 48.268,55.654
SW4 on Top Layer "TOP_LAYER_SW4_P050" (solid, remove dead copper, pour order 50): 43.491,97.767 43.491,91.065 43.058,90.632 38.751,90.632 36.73,88.611 36.73,84.291 47.86,84.291 47.86,97.427 47.52,97.767
SW3 on Top Layer "TOP_LAYER_SW3_P051" (solid, remove dead copper, pour order 51): 59.882,97.767 59.882,90.943 59.571,90.632 53.877,90.632 51.867,88.623 51.867,84.275 64.465,84.275 64.465,97.767
SR_Source on Top Layer "TOP_LAYER_SR_SOURCE_P052" (solid, remove dead copper, pour order 52): 41.429,100.467 41.386,100.416 41.386,98.134 41.414,98.105 42.688,98.105 43.122,98.539 47.666,98.539 47.733,98.606 47.733,100.364 47.627,100.471
SR_Source on Top Layer "TOP_LAYER_SR_SOURCE_P053" (solid, remove dead copper, pour order 53): 57.82,100.492 57.777,100.441 57.777,98.159 57.805,98.131 59.079,98.131 59.513,98.564 64.056,98.564 64.124,98.632 64.124,100.39 64.017,100.496
VOUT on Top Layer "TOP_LAYER_VOUT_P055" (solid, remove dead copper, pour order 55): 10.653,146.411 9.278,147.786 9.278,152.962 80.424,152.962 80.424,147.079 79.756,146.411
NetD9_2 on Top Layer "TOP_LAYER_NETD9_2_P076" (solid, remove dead copper, pour order 76): 17.925,50.265 21.557,50.265 22.165,50.873 22.165,55.654 20.304,55.654 20.062,55.896 20.062,58.687 19.785,58.963 15.588,58.963 15.429,58.804 15.429,57.278 16.465,57.278 17.925,55.818
GND on Top Layer "TOP_LAYER_GND_P077" (solid, remove dead copper, pour order 77): 14.447,43.441 14.447,45.44 14.614,45.607 16.238,45.607 16.397,45.448 16.397,43.441
GND on Top Layer "TOP_LAYER_GND_P078" (solid, remove dead copper, pour order 78): 22 vertices, not listed, extent 16.176,62.956 30.486,70.716
5V0_SEC on Top Layer "TOP_LAYER_5V0_SEC_P079" (solid, remove dead copper, pour order 79): 19.049,90.982 12.561,90.982 12.498,90.918 12.498,87.579 12.53,87.548 13.484,87.548 13.515,87.579 13.515,88.756 13.611,88.851 19.017,88.851 19.049,88.883
3V3_SEC on Top Layer "TOP_LAYER_3V3_SEC_P080" (solid, remove dead copper, pour order 80): 23.002,91.032 29.489,91.032 29.553,90.968 29.553,87.629 29.521,87.598 28.567,87.598 28.535,87.629 28.535,88.806 28.44,88.901 23.034,88.901 23.002,88.933
PRI_AGND on Top Layer "TOP_LAYER_PRI_AGND_P082" (solid, remove dead copper, pour order 82): 65.537,53.361 69.696,53.361 69.696,52.414 68.465,52.414 68.465,50.659 65.537,50.659
AGND on Top Layer "TOP_LAYER_AGND_P086" (solid, remove dead copper, pour order 86): 10.208,165.301 9.278,164.371 9.278,158.688 80.424,158.688 80.424,164.378 79.502,165.301
PRI_AGND on Top Layer "TOP_LAYER_PRI_AGND_P090" (solid, remove dead copper, pour order 90): 68.757,49.406 68.69,49.338 68.69,44.807 68.594,44.712 65.169,44.712 65,44.881 65,46.084 64.206,46.084 64.206,43.991 64.512,43.685 69.581,43.685 69.696,43.8 69.696,49.406
PRI_AGND on Top Layer "TOP_LAYER_PRI_AGND_P096" (solid, remove dead copper, pour order 96): 24.544,42.8 24.337,43.007 24.337,55.446 24.544,55.654 30.421,55.654 30.486,55.588 30.486,51.776 30.374,51.664 27.625,51.664 27.625,42.8
GND on Top Layer "TOP_LAYER_GND_P097" (solid, remove dead copper, pour order 97): 34.501,28.183 34.059,27.741 34.059,19.907 43.154,19.907 43.154,28.183
VIN_NEG on Top Layer "TOP_LAYER_VIN_NEG_P106" (solid, remove dead copper, pour order 106): 15.995,22.484 17.192,23.923 8.586,23.923 8.586,1.844 8.841,1.59 15.551,1.59 15.995,2.034
AGND on Top Layer "TOP_LAYER_AGND_P113" (solid, remove dead copper, pour order 113): 52.535,182.314 52.535,168.353 52.503,168.353 49.323,165.173 49.323,158.622 65.319,158.622 65.319,165.301 62.171,168.449 62.171,182.314
VIN_POS on Inside Layer 1 "INSIDE_LAYER_1_VIN_POS_P147" (solid, remove dead copper, pour order 147): 21 vertices, not listed, extent 20.48,-15.837 69.507,15.201
SR_AGND on Inside Layer 1 "INSIDE_LAYER_1_SR_AGND_P133" (solid, remove dead copper, pour order 133): 32.939,104.02 32.939,93.335 63.951,93.335 64.778,94.162 64.778,104.02
VIN_NEG on Inside Layer 1 "INSIDE_LAYER_1_VIN_NEG_P212" (solid, remove dead copper, pour order 212): 64.397,55.589 64.462,55.654 67.259,55.654 67.259,52.006 66.911,51.659 64.397,51.659
VIN_NEG on Inside Layer 1 "INSIDE_LAYER_1_VIN_NEG_P211" (solid, remove dead copper, pour order 211): 49.624,55.654 49.624,51.007 49.275,50.659 46.601,50.659 46.448,50.506 46.448,44.68 48.271,44.68 50.867,47.276 50.867,55.654
GND on Inside Layer 1 "INSIDE_LAYER_1_GND_P189" (solid, remove dead copper, pour order 189): 32.978,67.068 9.795,67.068 9,67.863 9,144.312 9.699,145.012 46.22,145.012 47.574,143.657 47.574,121.687 43.122,121.687 43.122,104.264 32.978,104.264
PRI_AGND on Inside Layer 1 "INSIDE_LAYER_1_PRI_AGND_P166" (solid, remove dead copper, pour order 166): 31.51,43.275 50.867,43.275 50.867,49.832 66.972,49.832 66.972,51.252 66.972,55.718 71.197,55.718 71.197,19.401 70.275,18.479 31.51,18.479
NetC1_2 on Inside Layer 1 "INSIDE_LAYER_1_NETC1_2_P194" (solid, remove dead copper, pour order 194): 36.889,57.736 36.889,62.427 48.348,62.427 48.348,57.736
SW3 on Inside Layer 1 "INSIDE_LAYER_1_SW3_P188" (solid, remove dead copper, pour order 188): 59.154,90.215 55.037,90.215 55.037,84.267 63.665,84.267 63.665,90.215
SW4 on Inside Layer 1 "INSIDE_LAYER_1_SW4_P187" (solid, remove dead copper, pour order 187): 43.026,90.628 37.899,90.628 37.899,84.282 47.828,84.282 47.828,90.628
HS_Drain on Inside Layer 1 "INSIDE_LAYER_1_HS_DRAIN_P178" (solid, remove dead copper, pour order 178): 37.811,50.166 35.649,50.166 35.649,44.728 37.811,44.728
HS_Drain on Inside Layer 1 "INSIDE_LAYER_1_HS_DRAIN_P177" (solid, remove dead copper, pour order 177): 55.206,55.654 52.607,55.654 52.607,51.644 55.111,51.644 55.206,51.74
VIN_NEG on Inside Layer 1 "INSIDE_LAYER_1_VIN_NEG_P172" (solid, remove dead copper, pour order 172): 16.058,26.68 8.65,26.68 8.65,1.717 8.904,1.463 15.614,1.463 16.058,1.907
SW2 on Inside Layer 1 "INSIDE_LAYER_1_SW2_P168" (solid, remove dead copper, pour order 168): 51.436,57.736 51.363,57.809 51.363,62.427 64.945,62.427 65.128,62.22 65.128,57.929 64.948,57.736 63.873,57.736 63.683,57.545 63.683,51.644 55.938,51.644 55.938,57.528 55.729,57.736
SW1 on Inside Layer 1 "INSIDE_LAYER_1_SW1_P165" (solid, remove dead copper, pour order 165): 36.996,51.931 36.889,52.038 36.889,54.005 36.977,54.093 48.242,54.093 48.348,53.986 48.348,52.056 48.223,51.931 46.019,51.931 45.784,51.696 45.784,44.712 38.479,44.712 38.479,51.867 38.415,51.931
VOUT on Inside Layer 1 "INSIDE_LAYER_1_VOUT_P154" (solid, remove dead copper, pour order 154): 62.139,127.628 52.655,127.628 52.655,128.277 52.655,146.557 51.529,147.683 8.046,147.683 8.046,154.902 62.139,154.902
VIN_NEG on Inside Layer 1 "INSIDE_LAYER_1_VIN_NEG_P146" (solid, remove dead copper, pour order 146): 23 vertices, not listed, extent 38.686,-15.551 81.124,55.643
AGND on Inside Layer 1 "INSIDE_LAYER_1_AGND_P140" (solid, remove dead copper, pour order 140): 70.757,124.122 70.757,165.078 70.979,165.301 80.933,165.301 81.219,165.014 81.219,118.147 80.846,117.716 71.08,117.716 70.757,118.001
AGND on Inside Layer 1 "INSIDE_LAYER_1_AGND_P119" (solid, remove dead copper, pour order 119): 41.723,165.237 41.723,158.624 80.361,158.624 80.361,164.315 79.438,165.237
AGND on Inside Layer 1 "INSIDE_LAYER_1_AGND_P120" (solid, remove dead copper, pour order 120): 52.471,182.25 52.471,168.29 52.44,168.29 49.259,165.11 49.259,158.559 65.255,158.559 65.255,165.237 62.107,168.385 62.107,182.25
SR_Drain on Layer 1 "LAYER_1_SR_DRAIN_P190" (solid, remove dead copper, pour order 190): 46.021,102.516 46.021,110.944 49.166,114.089 64.269,114.089 64.269,102.516 59.913,102.516 59.913,107.899 57.813,109.999 49.897,109.999 47.828,107.587 47.828,102.516
GND on Layer 1 "LAYER_1_GND_P198" (solid, remove dead copper, pour order 198): 35.191,69.027 33.232,67.068 9.795,67.068 9,67.863 9,144.312 9.699,145.012 46.22,145.012 47.574,143.657 47.574,122.846 44.001,119.73 44.001,105.07 35.191,105.07
VIN_NEG on Layer 1 "LAYER_1_VIN_NEG_P144" (solid, remove dead copper, pour order 144): 19 vertices, not listed, extent 8.586,2.353 81.06,56.446
SW3 on Layer 1 "LAYER_1_SW3_P184" (solid, remove dead copper, pour order 184): 59.882,95.876 59.882,90.943 59.154,90.215 55.037,90.215 55.037,84.238 63.665,84.238 63.665,95.876
SW4 on Layer 1 "LAYER_1_SW4_P181" (solid, remove dead copper, pour order 181): 43.459,95.876 43.459,91.061 42.038,89.64 38.017,89.64 38.017,84.296 47.828,84.296 47.828,95.876
VIN_NEG on Layer 1 "LAYER_1_VIN_NEG_P102" (solid, remove dead copper, pour order 102): 30 vertices, not listed, extent 8.287,-15.551 81.124,34.949
SR_Source on Layer 1 "LAYER_1_SR_SOURCE_P136" (solid, remove dead copper, pour order 136): 43.648,112.63 46.238,115.219 46.238,120.747 38.988,120.747 38.988,114.483 36.03,114.483 36.03,111.144 38.988,108.186 38.988,98.9 39.624,98.264 45.889,98.264 63.761,98.264 64.269,98.773 64.269,100.816 43.648,100.816
VIN_POS on Layer 1 "LAYER_1_VIN_POS_P156" (solid, remove dead copper, pour order 156): 69.586,15.264 69.586,6.996 55.906,6.996 55.906,10.812 55.27,11.448 33.86,11.448 32.935,10.523 32.935,7.396 20.512,7.396 20.512,14.509 21.298,15.296 52.376,15.296
VOUT on Layer 1 "LAYER_1_VOUT_P152" (solid, remove dead copper, pour order 152): 62.665,127.628 52.655,127.628 52.655,128.277 52.655,146.557 51.529,147.683 8.046,147.683 8.046,154.902 62.665,154.902
AGND on Layer 1 "LAYER_1_AGND_P141" (solid, remove dead copper, pour order 141): 70.852,124.122 70.852,165.078 71.202,165.428 80.901,165.428 81.315,165.014 81.315,118.147 80.941,117.716 71.176,117.716 70.852,118.001
AGND on Layer 1 "LAYER_1_AGND_P114" (solid, remove dead copper, pour order 114): 41.786,165.301 41.786,158.688 80.424,158.688 80.424,164.378 79.502,165.301
AGND on Layer 1 "LAYER_1_AGND_P115" (solid, remove dead copper, pour order 115): 52.535,182.314 52.535,168.353 52.503,168.353 49.323,165.173 49.323,158.622 65.319,158.622 65.319,165.301 62.171,168.449 62.171,182.314
VIN_POS on Layer 2 "LAYER_2_VIN_POS_P157" (solid, remove dead copper, pour order 157): 69.548,15.296 69.548,7.427 55.874,7.427 55.874,10.844 55.238,11.48 33.828,11.48 32.903,10.555 32.903,7.427 20.48,7.427 20.48,14.541 21.266,15.328 52.344,15.328
GND on Layer 2 "LAYER_2_GND_P160" (solid, remove dead copper, pour order 160): 31.96,67.068 9.763,67.068 8.968,67.863 8.968,144.312 9.667,145.012 44.776,145.012 44.776,121.113 31.96,121.113
VIN_NEG on Layer 2 "LAYER_2_VIN_NEG_P163" (solid, remove dead copper, pour order 163): 20.989,55.938 21.211,56.16 81.06,56.16 81.06,42.136 81.06,2.353 76.131,2.353 73.778,4.707 73.778,22.897 65.268,31.406 17.141,31.406 17.141,35.076 20.989,35.076
SR_Drain on Layer 2 "LAYER_2_SR_DRAIN_P202" (solid, remove dead copper, pour order 202): 46.021,102.471 46.021,110.944 49.166,114.089 64.269,114.089 64.269,102.471 59.913,102.471 59.913,107.899 57.813,109.999 49.897,109.999 47.828,107.587 47.828,102.471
